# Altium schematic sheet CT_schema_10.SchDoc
size 497 x 385 mm
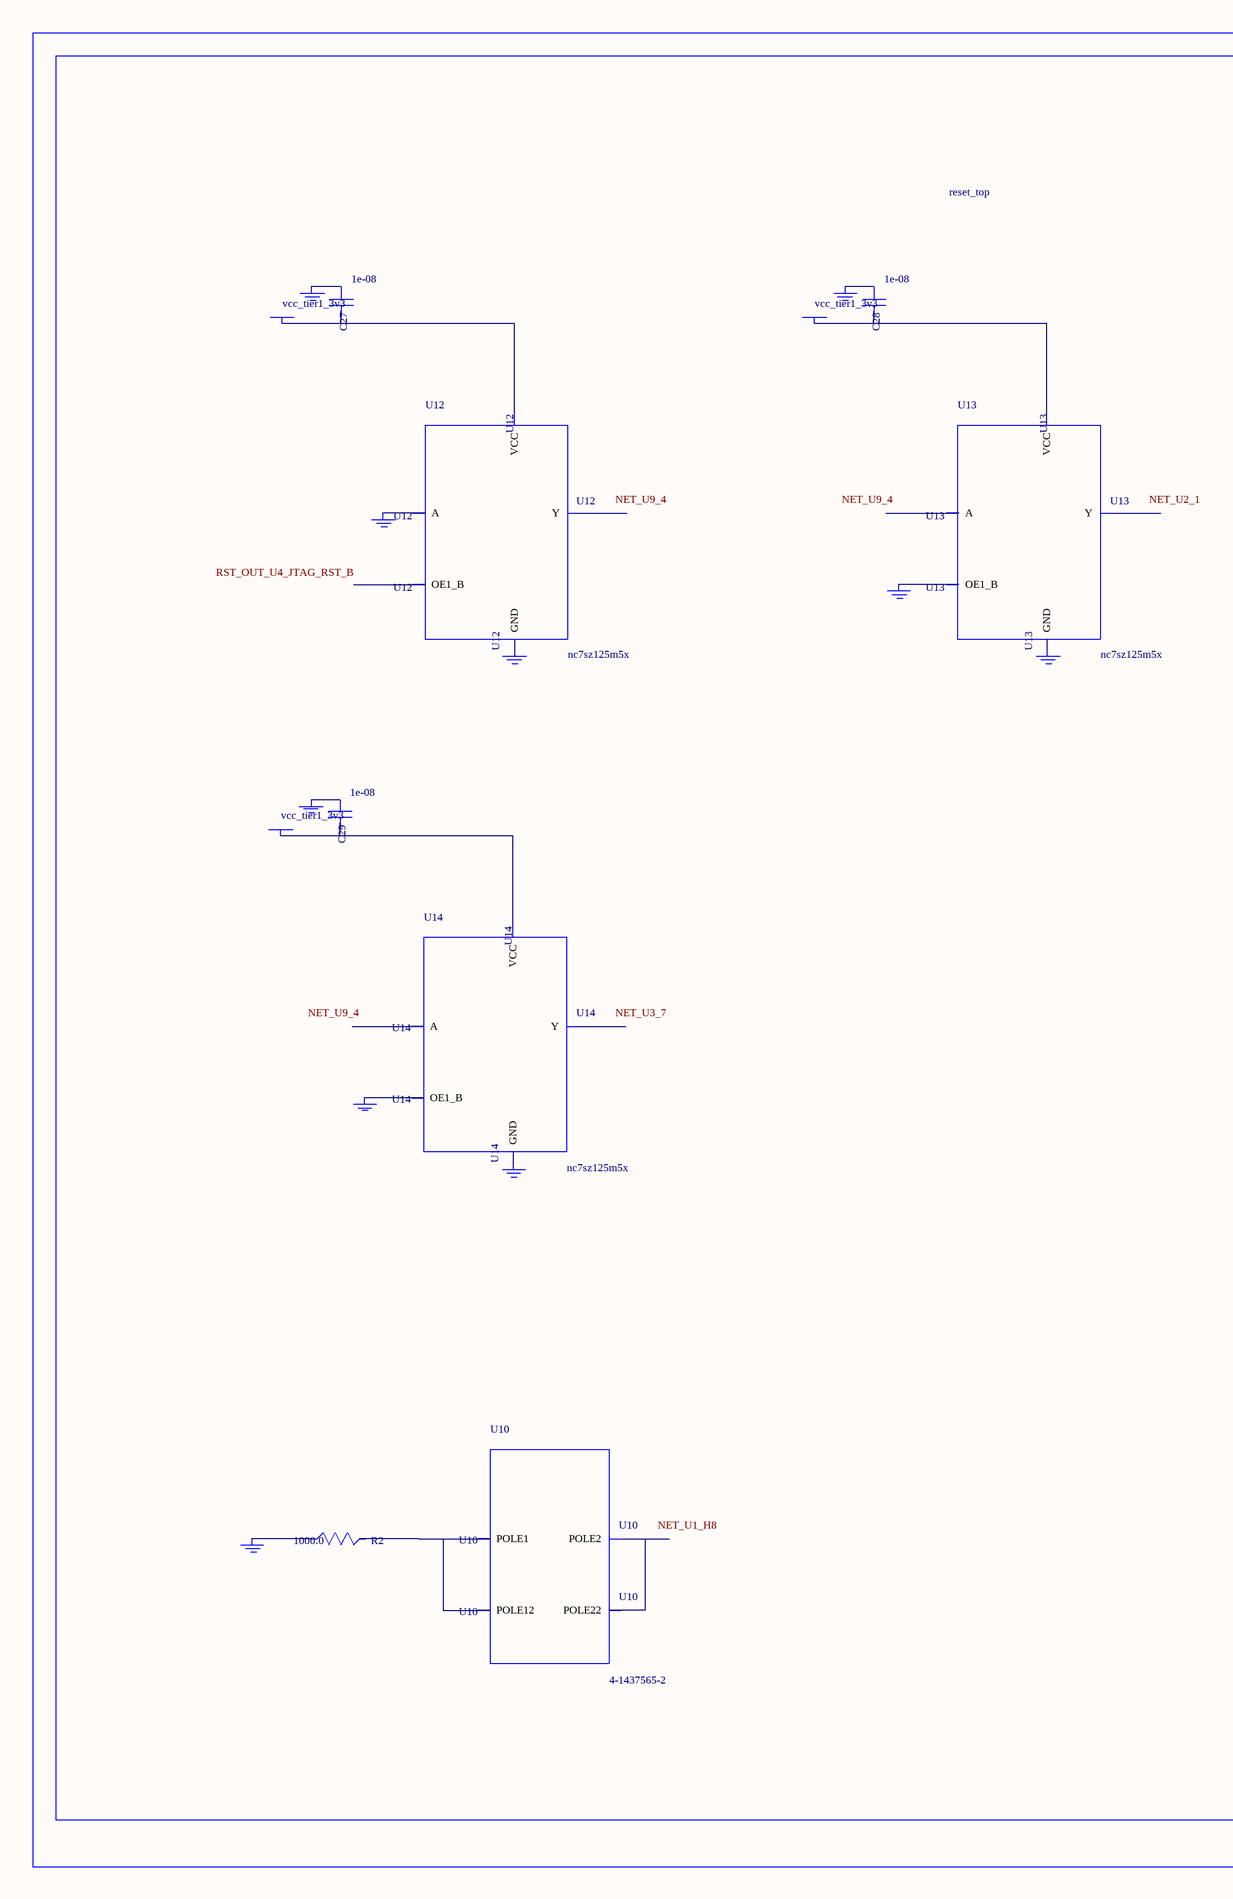
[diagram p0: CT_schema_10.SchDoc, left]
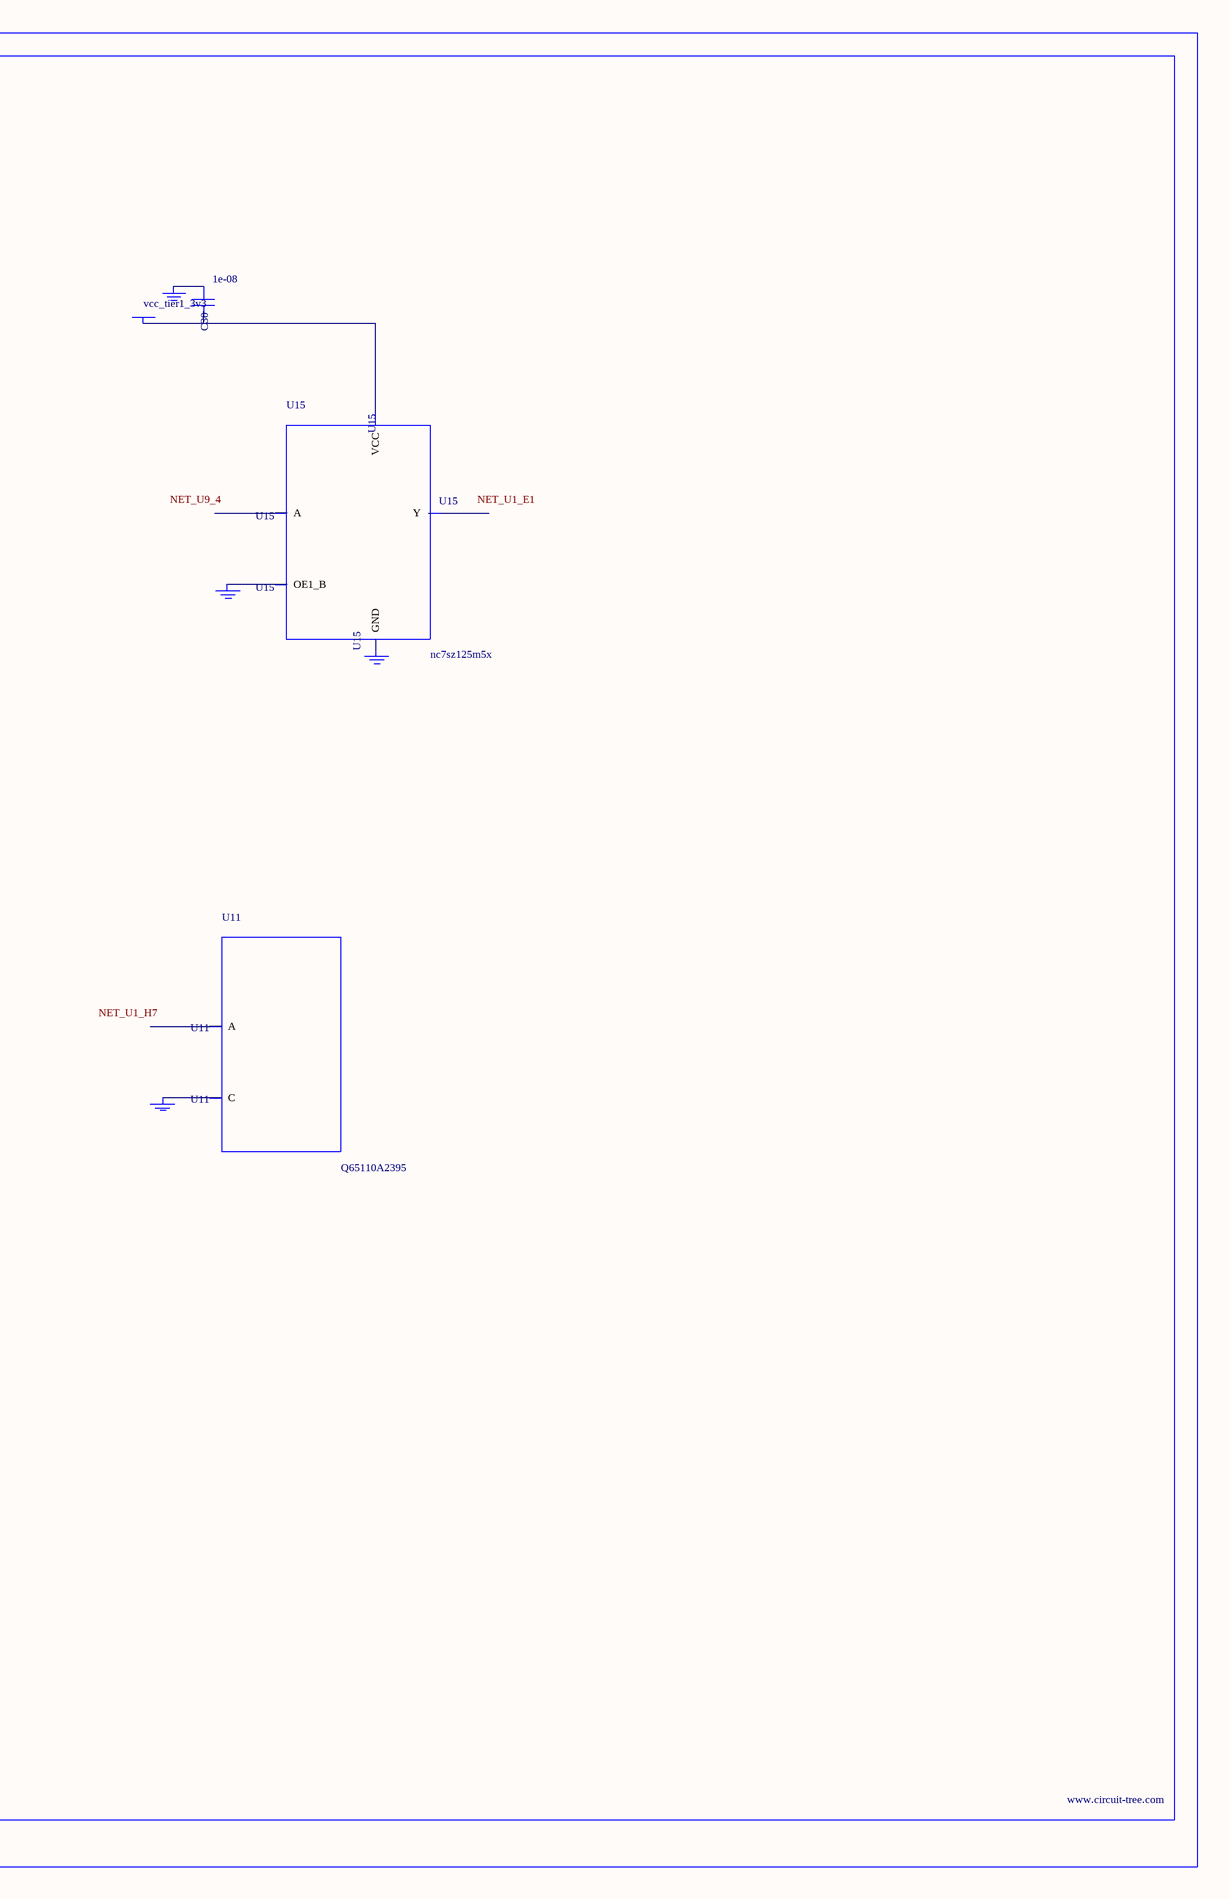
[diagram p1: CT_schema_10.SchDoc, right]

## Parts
BORDER9  (no value)
C27  1e-08  [C0402]
C28  1e-08  [C0402]
C29  1e-08  [C0402]
C30  1e-08  [C0402]
GND_INSTANCE_9_0  (no value)
GND_INSTANCE_9_1  (no value)
GND_INSTANCE_9_2  (no value)
GND_INSTANCE_9_3  (no value)
GND_INSTANCE_9_4  (no value)
GND_INSTANCE_9_5  (no value)
GND_INSTANCE_9_6  (no value)
GND_INSTANCE_9_7  (no value)
GND_INSTANCE_9_8  (no value)
GND_INSTANCE_9_9  (no value)
GND_INSTANCE_9_10  (no value)
GND_INSTANCE_9_11  (no value)
GND_INSTANCE_9_12  (no value)
GND_INSTANCE_9_13  (no value)
POWER_INSTANCE_9_0  vcc_tier1_3v3
POWER_INSTANCE_9_1  vcc_tier1_3v3
POWER_INSTANCE_9_2  vcc_tier1_3v3
POWER_INSTANCE_9_3  vcc_tier1_3v3
R2  1000.0  [R0603]
U10  4-1437565-2  [SW_4-1437565-2]
U11  Q65110A2395  [LGM67K-G1J2-24-Z]
U12  nc7sz125m5x  [NC7SZ125M5X]
U13  nc7sz125m5x  [NC7SZ125M5X]
U14  nc7sz125m5x  [NC7SZ125M5X]
U15  nc7sz125m5x  [NC7SZ125M5X]

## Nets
NetC27_1: C27.1 GND_INSTANCE_9_2.0(GND)
NetC27_2: C27.2 POWER_INSTANCE_9_0.0(PWR) U12.5(VCC)
NetC28_1: C28.1 GND_INSTANCE_9_5.0(GND)
NetC28_2: C28.2 POWER_INSTANCE_9_1.0(PWR) U13.5(VCC)
NetC29_1: C29.1 GND_INSTANCE_9_8.0(GND)
NetC29_2: C29.2 POWER_INSTANCE_9_2.0(PWR) U14.5(VCC)
NetC30_1: C30.1 GND_INSTANCE_9_11.0(GND)
NetC30_2: C30.2 POWER_INSTANCE_9_3.0(PWR) U15.5(VCC)
NetGND_INSTANCE_9_0_0: GND_INSTANCE_9_0.0(GND) R2.1
NetGND_INSTANCE_9_1_0: GND_INSTANCE_9_1.0(GND) U11.C
NetGND_INSTANCE_9_3_0: GND_INSTANCE_9_3.0(GND) U12.2(A)
NetGND_INSTANCE_9_4_0: GND_INSTANCE_9_4.0(GND) U12.3(GND)
NetGND_INSTANCE_9_6_0: GND_INSTANCE_9_6.0(GND) U13.1(OE1_B)
NetGND_INSTANCE_9_7_0: GND_INSTANCE_9_7.0(GND) U13.3(GND)
NetGND_INSTANCE_9_9_0: GND_INSTANCE_9_9.0(GND) U14.1(OE1_B)
NetGND_INSTANCE_9_10_0: GND_INSTANCE_9_10.0(GND) U14.3(GND)
NetGND_INSTANCE_9_12_0: GND_INSTANCE_9_12.0(GND) U15.1(OE1_B)
NetGND_INSTANCE_9_13_0: GND_INSTANCE_9_13.0(GND) U15.3(GND)
NetR2_2: R2.2 U10.1(POLE1) U10.2(POLE12)
NetU10_3: U10.3(POLE2) U10.4(POLE22)

Not connected (* = marked no-connect by the designer): U11 A; U12 1(OE1_B) 4(Y); U13 2(A) 4(Y); U14 2(A) 4(Y); U15 2(A) 4(Y)

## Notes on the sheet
- Labels drawn without touching a wire or pin: NET_U1_E1, NET_U1_H7, NET_U1_H8, NET_U2_1, NET_U3_7, NET_U9_4, RST_OUT_U4_JTAG_RST_B

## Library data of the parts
BORDER9 = BORDER_PAGE9
C27-C30 = C0402C103K3RAC
GND_INSTANCE_9_0-GND_INSTANCE_9_13 = GND
POWER_INSTANCE_9_0-POWER_INSTANCE_9_3 = PWR
R2 = RC0603JR-071KL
